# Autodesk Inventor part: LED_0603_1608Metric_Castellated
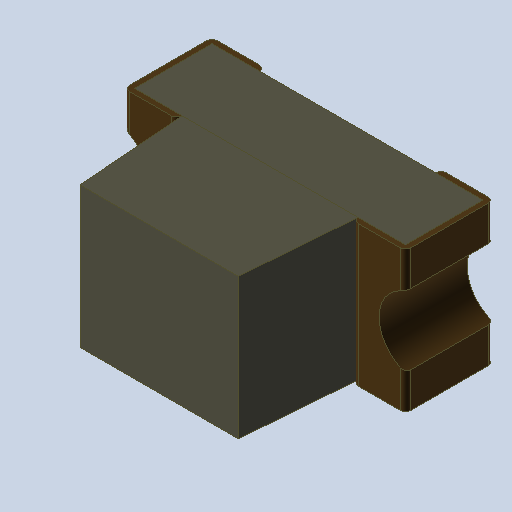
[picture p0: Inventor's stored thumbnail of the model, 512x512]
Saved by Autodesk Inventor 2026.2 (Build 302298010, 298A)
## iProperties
Created: 2026-10
Part Number: LED_0603_1608Metric_Castellated
Material: Générique
Document SubType Name: Modeling
Designer: mel
Density: 1 g/cm^3
Appearance: Par défaut
Author: mel
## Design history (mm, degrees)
feature "Base1"
node "Solide1"
